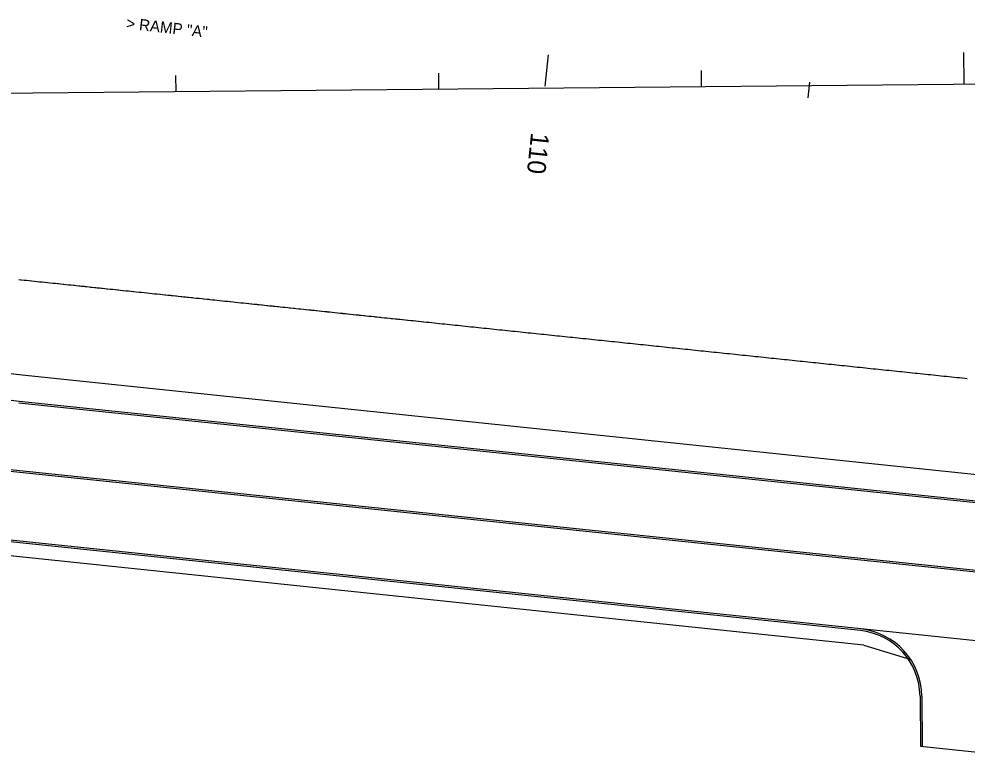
# Model space of a CAD drawing. Extents: x 2145147 to 2158018, y 137519 to 148068.
# Drawn here: x 2148648.2 to 2149009.1, y 142821.5 to 143100.9 of the extents above; entities that cross this region are included whole.
import ezdxf

# ---------------------------------------------------------------- set-up
doc = ezdxf.new("R2010")
doc.units = 0
for name, color, linetype in [('EX_Align_1', 7, 'Continuous'), ('PR_Align_Ramp_A', 7, 'Continuous'), ('PR_Align_Ramp_A_Label', 7, 'Continuous'), ('PR_Align_Ramp_A_Sta', 7, 'Continuous'), ('PR_Phasing_Pavement_6', 7, 'Continuous')]:
    doc.layers.add(name, color=color, linetype=linetype)

msp = doc.modelspace()

# ---------------------------------------------------------------- linework, layer by layer
at = {"layer": 'EX_Align_1'}
msp.add_line((2148007.93, 143066.66), (2149507.86, 143080.88), dxfattribs=at)
for points in [[(2149007.77, 143088.14), (2149007.88, 143076.14)], [(2148707.84, 143079.3), (2148707.9, 143073.3)], [(2148807.83, 143080.24), (2148807.89, 143074.24)], [(2148907.83, 143081.19), (2148907.89, 143075.19)]]:
    msp.add_lwpolyline(points, dxfattribs=at)
at = {"layer": 'PR_Align_Ramp_A'}
for points in [[(2148848.5, 143075.31), (2148849.74, 143087.24)], [(2148948.58, 143070.9), (2148949.2, 143076.87)]]:
    msp.add_lwpolyline(points, dxfattribs=at)
at = {"layer": 'PR_Phasing_Pavement_6'}
for p, q in [((2148384.89, 142986.71), (2148648.27, 142955.44)), ((2149379.97, 142851.96), (2148388.45, 142955.4)), ((2149380.04, 142852.62), (2148388.52, 142956.06)), ((2148648.27, 142955.44), (2149307.21, 142886.7)), ((2148648.2, 142954.77), (2149307.14, 142886.03)), ((2149377.28, 142826.1), (2148385.76, 142929.54)), ((2148968.45, 142868.08), (2148520.77, 142914.78)), ((2148969.79, 142862.58), (2148523.9, 142909.09)), ((2148969.79, 142862.58), (2148987.64, 142857.03)), ((2148991.16, 142843.14), (2148991.36, 142824.13)), ((2148991.82, 142843.15), (2148992.02, 142824.06)), ((2148991.36, 142824.13), (2149016.72, 142821.49))]:
    msp.add_line(p, q, dxfattribs=at)
for points in [[(2148354.64, 143000.38), (2148649.38, 142965.38), (2149308.25, 142896.64)], [(2148648.14, 143001.7), (2148648.92, 143001.62), (2148649.13, 143001.6), (2148650.12, 143001.49), (2148650.95, 143001.41), (2148651.11, 143001.39), (2148652.1, 143001.29), (2148652.98, 143001.2), (2148653.09, 143001.18), (2148653.11, 143001.18), (2148653.12, 143001.18), (2148654.08, 143001.08), (2148655.02, 143000.98), (2148655.08, 143000.98), (2148656.07, 143000.87), (2148657.06, 143000.77), (2148658.06, 143000.67), (2148659.05, 143000.56), (2148659.11, 143000.56), (2148660.05, 143000.46), (2148661.04, 143000.35), (2148661.15, 143000.34), (2148661.74, 143000.28), (2148662.04, 143000.25), (2148663.03, 143000.15), (2148663.2, 143000.13), (2148664.03, 143000.04), (2148665.02, 142999.94), (2148665.24, 142999.92), (2148666.02, 142999.84), (2148667.01, 142999.73), (2148667.28, 142999.7), (2148668.01, 142999.63), (2148669, 142999.52), (2148669.33, 142999.49), (2148669.99, 142999.42), (2148670.99, 142999.32), (2148671.37, 142999.28), (2148671.98, 142999.21), (2148672.98, 142999.11), (2148673.41, 142999.06), (2148673.97, 142999.01), (2148674.97, 142998.9), (2148675.46, 142998.85), (2148675.96, 142998.8), (2148676.96, 142998.69), (2148677.5, 142998.64), (2148677.95, 142998.59), (2148678.95, 142998.49), (2148679.55, 142998.42), (2148679.94, 142998.38), (2148680.93, 142998.28), (2148681.59, 142998.21), (2148681.93, 142998.18), (2148682.92, 142998.07), (2148683.63, 142998), (2148683.92, 142997.97), (2148684.91, 142997.86), (2148685.68, 142997.79), (2148685.91, 142997.76), (2148686.9, 142997.66), (2148687.72, 142997.57), (2148687.9, 142997.55), (2148688.89, 142997.45), (2148689.76, 142997.36), (2148689.89, 142997.35), (2148690.88, 142997.24), (2148691.81, 142997.15), (2148691.88, 142997.14), (2148692.87, 142997.03), (2148693.85, 142996.93), (2148693.86, 142996.93), (2148694.86, 142996.83), (2148695.85, 142996.72), (2148695.89, 142996.72), (2148696.85, 142996.62), (2148697.84, 142996.52), (2148697.94, 142996.51), (2148698.84, 142996.41), (2148699.83, 142996.31), (2148699.98, 142996.29), (2148700.83, 142996.2), (2148701.82, 142996.1), (2148702.03, 142996.08), (2148702.82, 142996), (2148703.81, 142995.89), (2148704.07, 142995.87), (2148704.81, 142995.79), (2148705.8, 142995.69), (2148706.11, 142995.65), (2148706.79, 142995.58), (2148707.79, 142995.48), (2148708.16, 142995.44), (2148708.78, 142995.37), (2148709.78, 142995.27), (2148710.2, 142995.23), (2148710.77, 142995.17), (2148711.77, 142995.06), (2148712.24, 142995.01), (2148712.76, 142994.96), (2148713.76, 142994.86), (2148714.29, 142994.8), (2148714.75, 142994.75), (2148715.75, 142994.65), (2148716.33, 142994.59), (2148716.74, 142994.54), (2148717.74, 142994.44), (2148718.38, 142994.37), (2148718.73, 142994.34), (2148719.72, 142994.23), (2148720.42, 142994.16), (2148720.72, 142994.13), (2148721.71, 142994.03), (2148722.46, 142993.95), (2148722.71, 142993.92), (2148723.7, 142993.82), (2148724.51, 142993.73), (2148724.7, 142993.71), (2148725.69, 142993.61), (2148726.55, 142993.52), (2148726.69, 142993.51), (2148727.68, 142993.4), (2148728.59, 142993.31), (2148728.68, 142993.3), (2148729.67, 142993.2), (2148730.64, 142993.09), (2148730.67, 142993.09), (2148731.66, 142992.99), (2148732.65, 142992.88), (2148732.68, 142992.88), (2148733.65, 142992.78), (2148734.64, 142992.68), (2148734.73, 142992.67), (2148735.64, 142992.57), (2148736.63, 142992.47), (2148736.77, 142992.45), (2148737.63, 142992.37), (2148738.62, 142992.26), (2148738.81, 142992.24), (2148739.62, 142992.16), (2148740.61, 142992.05), (2148740.86, 142992.03), (2148741.61, 142991.95), (2148742.6, 142991.85), (2148742.9, 142991.82), (2148743.59, 142991.74), (2148744.59, 142991.64), (2148744.94, 142991.6), (2148745.58, 142991.54), (2148746.58, 142991.43), (2148746.99, 142991.39), (2148747.57, 142991.33), (2148748.57, 142991.22), (2148749.03, 142991.18), (2148749.56, 142991.12), (2148750.56, 142991.02), (2148751.07, 142990.96), (2148751.55, 142990.91), (2148752.55, 142990.81), (2148753.12, 142990.75), (2148753.54, 142990.71), (2148754.54, 142990.6), (2148755.16, 142990.54), (2148755.53, 142990.5), (2148756.52, 142990.39), (2148757.21, 142990.32), (2148757.52, 142990.29), (2148758.51, 142990.19), (2148759.25, 142990.11), (2148759.51, 142990.08), (2148760.5, 142989.98), (2148761.29, 142989.9), (2148761.5, 142989.88), (2148762.49, 142989.77), (2148763.34, 142989.68), (2148763.49, 142989.67), (2148764.48, 142989.56), (2148765.38, 142989.47), (2148765.48, 142989.46), (2148766.47, 142989.36), (2148767.42, 142989.26), (2148767.47, 142989.25), (2148768.46, 142989.15), (2148769.45, 142989.05), (2148769.47, 142989.04), (2148770.45, 142988.94), (2148771.44, 142988.84), (2148771.51, 142988.83), (2148772.44, 142988.73), (2148773.43, 142988.63), (2148773.56, 142988.62), (2148774.43, 142988.53), (2148775.42, 142988.42), (2148775.6, 142988.4), (2148776.42, 142988.32), (2148777.41, 142988.21), (2148777.64, 142988.19), (2148778.41, 142988.11), (2148779.4, 142988.01), (2148779.69, 142987.98), (2148780.4, 142987.9), (2148781.39, 142987.8), (2148781.73, 142987.76), (2148782.38, 142987.7), (2148783.38, 142987.59), (2148783.77, 142987.55), (2148784.37, 142987.49), (2148785.37, 142987.38), (2148785.82, 142987.34), (2148786.36, 142987.28), (2148787.36, 142987.18), (2148787.86, 142987.12), (2148788.35, 142987.07), (2148789.35, 142986.97), (2148789.91, 142986.91), (2148790.34, 142986.87), (2148791.34, 142986.76), (2148791.95, 142986.7), (2148792.33, 142986.66), (2148793.33, 142986.55), (2148793.99, 142986.49), (2148794.32, 142986.45), (2148795.31, 142986.35), (2148796.04, 142986.27), (2148796.31, 142986.24), (2148797.3, 142986.14), (2148798.08, 142986.06), (2148798.3, 142986.04), (2148799.29, 142985.93), (2148800.12, 142985.85), (2148800.29, 142985.83), (2148801.28, 142985.72), (2148802.17, 142985.63), (2148802.28, 142985.62), (2148803.27, 142985.52), (2148804.21, 142985.42), (2148804.27, 142985.41), (2148805.26, 142985.31), (2148806.25, 142985.21), (2148807.25, 142985.1), (2148808.24, 142985), (2148809.24, 142984.89), (2148810.23, 142984.79), (2148811.23, 142984.69), (2148812.22, 142984.58), (2148813.22, 142984.48), (2148814.21, 142984.38), (2148815.21, 142984.27), (2148816.2, 142984.17), (2148817.2, 142984.06), (2148818.19, 142983.96), (2148819.18, 142983.86), (2148820.18, 142983.75), (2148821.17, 142983.65), (2148822.17, 142983.55), (2148823.16, 142983.44), (2148824.16, 142983.34), (2148825.15, 142983.23), (2148826.15, 142983.13), (2148827.14, 142983.03), (2148828.14, 142982.92), (2148829.13, 142982.82), (2148830.13, 142982.72), (2148831.12, 142982.61), (2148832.11, 142982.51), (2148833.11, 142982.4), (2148834.1, 142982.3), (2148835.1, 142982.2), (2148836.09, 142982.09), (2148837.09, 142981.99), (2148838.08, 142981.89), (2148839.08, 142981.78), (2148840.07, 142981.68), (2148841.07, 142981.57), (2148842.06, 142981.47), (2148843.06, 142981.37), (2148844.05, 142981.26), (2148845.04, 142981.16), (2148846.04, 142981.06), (2148847.03, 142980.95), (2148848.03, 142980.85), (2148849.02, 142980.74), (2148850.02, 142980.64), (2148851.01, 142980.54), (2148852.01, 142980.43), (2148853, 142980.33), (2148854, 142980.23), (2148854.99, 142980.12), (2148855.98, 142980.02), (2148856.98, 142979.91), (2148857.97, 142979.81), (2148858.97, 142979.71), (2148859.96, 142979.6), (2148860.96, 142979.5), (2148861.95, 142979.4), (2148862.95, 142979.29), (2148863.94, 142979.19), (2148864.94, 142979.08), (2148865.93, 142978.98), (2148866.93, 142978.88), (2148867.92, 142978.77), (2148868.91, 142978.67), (2148869.91, 142978.57), (2148870.9, 142978.46), (2148871.9, 142978.36), (2148872.89, 142978.25), (2148873.89, 142978.15), (2148874.88, 142978.05), (2148875.88, 142977.94), (2148876.87, 142977.84), (2148877.87, 142977.74), (2148878.86, 142977.63), (2148879.86, 142977.53), (2148880.85, 142977.42), (2148881.84, 142977.32), (2148882.84, 142977.22), (2148883.83, 142977.11), (2148884.83, 142977.01), (2148885.82, 142976.91), (2148886.82, 142976.8), (2148887.81, 142976.7), (2148888.81, 142976.59), (2148889.8, 142976.49), (2148890.8, 142976.39), (2148891.79, 142976.28), (2148892.79, 142976.18), (2148893.78, 142976.08), (2148894.77, 142975.97), (2148895.77, 142975.87), (2148896.76, 142975.76), (2148897.76, 142975.66), (2148898.75, 142975.56), (2148899.75, 142975.45), (2148900.74, 142975.35), (2148901.74, 142975.25), (2148902.73, 142975.14), (2148903.73, 142975.04), (2148904.72, 142974.93), (2148905.72, 142974.83), (2148906.71, 142974.73), (2148907.7, 142974.62), (2148908.7, 142974.52), (2148909.69, 142974.41), (2148910.69, 142974.31), (2148911.68, 142974.21), (2148912.68, 142974.1), (2148913.67, 142974), (2148914.67, 142973.9), (2148915.66, 142973.79), (2148916.66, 142973.69), (2148917.65, 142973.58), (2148918.64, 142973.48), (2148919.64, 142973.38), (2148920.63, 142973.27), (2148921.63, 142973.17), (2148922.62, 142973.07), (2148923.62, 142972.96), (2148924.61, 142972.86), (2148925.61, 142972.75), (2148926.6, 142972.65), (2148927.6, 142972.55), (2148928.59, 142972.44), (2148929.59, 142972.34), (2148930.58, 142972.24), (2148931.57, 142972.13), (2148932.57, 142972.03), (2148933.56, 142971.92), (2148934.56, 142971.82), (2148935.55, 142971.72), (2148936.55, 142971.61), (2148937.54, 142971.51), (2148938.54, 142971.41), (2148939.53, 142971.3), (2148940.53, 142971.2), (2148941.52, 142971.09), (2148942.52, 142970.99), (2148943.51, 142970.89), (2148944.5, 142970.78), (2148945.5, 142970.68), (2148946.49, 142970.58), (2148947.49, 142970.47), (2148948.48, 142970.37), (2148949.48, 142970.26), (2148950.47, 142970.16), (2148951.47, 142970.06), (2148952.46, 142969.95), (2148953.46, 142969.85), (2148954.45, 142969.75), (2148955.45, 142969.64), (2148956.44, 142969.54), (2148957.43, 142969.43), (2148958.43, 142969.33), (2148959.42, 142969.23), (2148960.42, 142969.12), (2148961.41, 142969.02), (2148962.41, 142968.92), (2148963.4, 142968.81), (2148964.4, 142968.71), (2148965.39, 142968.6), (2148966.39, 142968.5), (2148967.38, 142968.4), (2148968.38, 142968.29), (2148969.37, 142968.19), (2148970.36, 142968.09), (2148971.36, 142967.98), (2148972.35, 142967.88), (2148973.35, 142967.77), (2148974.34, 142967.67), (2148975.34, 142967.57), (2148976.33, 142967.46), (2148977.33, 142967.36), (2148978.32, 142967.26), (2148979.32, 142967.15), (2148980.31, 142967.05), (2148981.3, 142966.94), (2148982.3, 142966.84), (2148983.29, 142966.74), (2148984.29, 142966.63), (2148985.28, 142966.53), (2148986.28, 142966.43), (2148987.27, 142966.32), (2148988.27, 142966.22), (2148989.26, 142966.11), (2148990.26, 142966.01), (2148991.25, 142965.91), (2148992.25, 142965.8), (2148993.24, 142965.7), (2148994.23, 142965.6), (2148995.23, 142965.49), (2148996.22, 142965.39), (2148997.22, 142965.28), (2148998.21, 142965.18), (2148999.21, 142965.08), (2149000.2, 142964.97), (2149001.2, 142964.87), (2149002.19, 142964.77), (2149003.19, 142964.66), (2149004.18, 142964.56), (2149005.18, 142964.45), (2149006.17, 142964.35), (2149007.16, 142964.25), (2149008.16, 142964.14), (2149009.15, 142964.04)]]:
    msp.add_lwpolyline(points, dxfattribs=at)
for radius in [26, 25.33]:
    msp.add_arc((2148965.83, 142842.88), radius, 0.5969, 84.0443, dxfattribs=at)

# ---------------------------------------------------------------- texts
at = {"layer": 'PR_Align_Ramp_A_Label'}
msp.add_text('> RAMP "A"', height=4.3, rotation=353.5391, dxfattribs=at).set_placement((2148688.82, 143097.2))
at = {"layer": 'PR_Align_Ramp_A_Sta'}
msp.add_text('110', height=7, rotation=264.0443, dxfattribs=at).set_placement((2148843.15, 143057.77))

doc.saveas('drawing.dxf')
